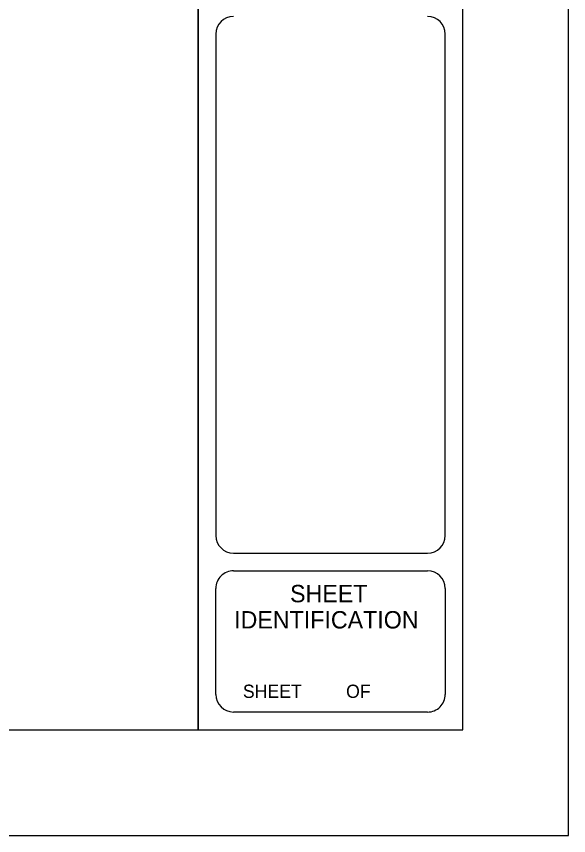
# Model space of a CAD drawing. Extents: x 0 to 3.33, y 0 to 2.33.
# Drawn here: x 3.0072 to 3.3333, y 0 to 0.4833 of the extents above; entities that cross this region are included whole.
import ezdxf

# ---------------------------------------------------------------- set-up
doc = ezdxf.new("R2010")
doc.units = 0
for name, color, linetype in [('G-ANNO-NPLT', 7, 'Continuous'), ('G-ANNO-TEXT', 7, 'Continuous'), ('G-ANNO-TTLB', 7, 'Continuous')]:
    doc.layers.add(name, color=color, linetype=linetype)

msp = doc.modelspace()

# ---------------------------------------------------------------- linework, layer by layer
at = {"layer": 'G-ANNO-NPLT'}
msp.add_lwpolyline([(0, 0), (3.333333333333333, 0), (3.333333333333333, 2.333333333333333), (0, 2.333333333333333)], close=True, dxfattribs=at)
at = {"layer": 'G-ANNO-TTLB'}
for points in [[(0.12500566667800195, 0.06250367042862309), (3.114589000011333, 0.06250367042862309), (3.114589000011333, 2.2708370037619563), (0.12500566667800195, 2.2708370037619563)], [(3.114589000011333, 0.06250367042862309), (3.270839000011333, 0.06250367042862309), (3.270839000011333, 2.2708370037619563), (3.114589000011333, 2.2708370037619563)]]:
    msp.add_lwpolyline(points, close=True, dxfattribs=at)
for points in [[(3.125005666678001, 0.4729203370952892), (3.125005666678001, 0.17708700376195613)], [(3.260422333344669, 0.17708700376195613), (3.260422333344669, 0.4729203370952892)], [(3.135422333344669, 0.16667033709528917), (3.250005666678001, 0.16667033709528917)], [(3.135413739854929, 0.1562536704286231), (3.2499970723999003, 0.1562536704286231)], [(3.1250142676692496, 0.08333413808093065), (3.1249970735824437, 0.14583413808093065)], [(3.2604137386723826, 0.1458398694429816), (3.2604309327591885, 0.08333986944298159)], [(3.2500142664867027, 0.07292033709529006), (3.135430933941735, 0.07292033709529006)]]:
    msp.add_lwpolyline(points, dxfattribs=at)
for centre, radius, start, end in [((3.135422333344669, 0.4729203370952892), 0.010416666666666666, 90, 180), ((3.250005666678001, 0.4729203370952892), 0.010416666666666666, 0, 90), ((3.135422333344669, 0.17708700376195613), 0.010416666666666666, 180, 270), ((3.250005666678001, 0.17708700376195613), 0.010416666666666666, 270, 0), ((3.135413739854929, 0.14583700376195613), 0.010416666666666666, 90, 180.0157623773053), ((3.2499970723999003, 0.14583700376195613), 0.010416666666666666, 0.015762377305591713, 90), ((3.135430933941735, 0.08333700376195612), 0.010416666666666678, 180.01576237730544, 270), ((3.2500142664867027, 0.08333700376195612), 0.010416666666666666, 270, 0.015762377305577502)]:
    msp.add_arc(centre, radius, start, end, dxfattribs=at)

# ---------------------------------------------------------------- texts
at = {"layer": 'G-ANNO-TEXT'}
for s, height, p in [('SHEET', 0.010253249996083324, (3.1688189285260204, 0.1376670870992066)), ('IDENTIFICATION', 0.010253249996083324, (3.1357967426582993, 0.12220550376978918)), ('SHEET         OF  ', 0.007812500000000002, (3.140944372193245, 0.0812536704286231))]:
    msp.add_text(s, height=height, dxfattribs=at).set_placement(p)

doc.saveas('drawing.dxf')
